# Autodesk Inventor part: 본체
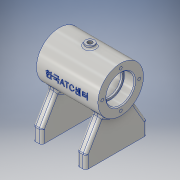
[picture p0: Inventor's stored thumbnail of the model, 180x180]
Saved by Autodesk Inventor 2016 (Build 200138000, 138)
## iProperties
Created: 2018-05
Part Number: 본체
Material: 알루미늄 6061
Document SubType Name: Modeling
Designer: USER
Mass: 317.695 g
Surface Area: 375.824 cm^2
Volume: 117.665 cm^3
Density: 2.7 g/cm^3
Appearance: 알루미늄 - 평지
Author: USER
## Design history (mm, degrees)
sketch "스케치1"
  geometry: L1 (-35, 0)-(35, 0); L2 (-35, 16)-(-35, 26); L3 (-35, 26)-(35, 26); L4 (35, 26)-(35, 16); L5 (35, 16)-(23, 16); L6 (23, 16)-(23, 14); L7 (23, 14)-(21, 14); L8 (21, 14)-(21, 21); L9 (21, 21)-(-21, 21); L10 (-21, 21)-(-21, 14); L11 (-21, 14)-(-23, 14); L12 (-23, 14)-(-23, 16); L13 (-23, 16)-(-35, 16); 2 further points
  constraints: 26 end point, 10 perpendicular, 2 point on line, 2 vertical, 1 coincident, 1 collinear, 1 horizontal, 1 midpoint
  dimensions: "d11" = 70 distance of L1.start L1.end; "d12" = 32 diameter of L13 L1; "d13" = 28 diameter of L11 L1; "d14" = 32 diameter of L5 L1; "d15" = 28 diameter of L7 L1; "d16" = 42 diameter of L9 L1; "d17" = 52 diameter of L3 L1; "d18" = 12 distance between parallel lines of L2 L12; "d19" = 12 distance of L4.end L5.end; "d20" = 42 distance of L8.end L9.end
revolve "회전1" sketch "스케치1" stored, may be unused: angle "d21" = 90 deg
node "작업 평면1"
sketch "스케치2"
  geometry: L1 (35, 26)-(35, -26) reference; C1 r 5 at (0, 0); 1 further point
  constraints: 1 centre point, 1 coincident
  dimensions: "d23" = 35 distance from line of C1.centre L1; "d24" = 10 diameter of C1
extrude "돌출1" join sketch "스케치2" stored distance "d25" = 0; taper "d26" = 0 deg
hole "구멍1" diameter "d29" = 5.188; stored, may be unused: countersink angle "d33" = 90 deg, drill point angle "d35" = 118 deg; dims "d27" = 10, "d28" = 10, "d30" = 12, "d31" = 4, "d32" = 2, "d34" = 16
sketch "스케치3"
  geometry: L1 (29, -5)-(25.515, -5) reference; L2 (25.515, 5)-(29, 5) reference; L3 (29, 5)-(29, 2.594) reference; L4 (29, 2.594)-(20.839, 2.594) reference; L5 (20.839, -2.594)-(29, -2.594) reference; L6 (29, -2.594)-(29, -5) reference; L7 (0, 0)-(-39.442, 0); L8 (0, 0)-(-27.251, -9.919); A1 r 26 centre (0, 0) between (25.515, 5) and (25.515, -5) reference; A2 r 21 centre (0, 0) between (20.839, 2.594) and (20.839, -2.594) reference; 1 further point
  constraints: 4 end point, 1 horizontal
  dimensions: "d36" = 20 deg angle of L7 L8; "d37" = 29 distance of L7.start L8.end
  node "절단 모서리 투영1"
node "작업 평면2"
sketch "스케치4"
  geometry: C1 r 6 at (0, 0); 2 further points
  constraints: 1 centre point, 1 coincident
  dimensions: "d38" = 12 diameter of C1
extrude "돌출2" join sketch "스케치4" stored distance "d39" = 10; taper "d40" = 0 deg
hole "구멍2" diameter "d43" = 5.188; stored, may be unused: countersink angle "d47" = 90 deg, drill point angle "d49" = 118 deg; dims "d41" = 10, "d42" = 10, "d44" = 12, "d45" = 4, "d46" = 2, "d48" = 16
node "작업 평면3"
sketch "스케치5"
  geometry: L1 (-19.386, 17.325)-(-50, 35); L2 (-50, 35)-(-65, 35); L3 (-65, 35)-(-65, -35); L4 (-65, -35)-(-50, -35); L5 (-50, -35)-(-19.386, -17.325); C1 r 16 at (0, 0) reference; A1 r 26 centre (0, 0) between (-19.386, 17.325) and (-19.386, -17.325) reference; A2 r 26 centre (0, 0) between (-19.386, 17.325) and (-19.386, -17.325) reference; 1 further point
  constraints: 10 end point, 4 point on circle, 2 perpendicular, 1 horizontal, 1 parallel
  dimensions: "d51" = 65 distance from line of L3 point (0, 0); "d52" = 15 distance of L1.end L2.end; "d53" = 30 deg angle of L1 L2; "d54" = 30 deg angle of L4 L5; "d55" = 70 distance of L2.end L3.end; "d56" = 35 distance from line of L4 point (0, 0)
extrude "돌출3" join sketch "스케치5" stored distance "d57" = 10; taper "d58" = 0 deg
sketch "스케치6" dims "d59" = 42
  geometry: 3 further points
  constraints: 2 vertical alignment, 1 coincident, 2 other
hole "구멍3" sketch "스케치6" at (0, 21) diameter "d60" = 3.242; stored, may be unused: countersink angle "d64" = 90 deg, drill point angle "d66" = 118 deg; dims "d61" = 8, "d62" = 4, "d63" = 2, "d65" = 10
sketch "스케치7"
  geometry: L1 (60, 70)-(50, 70) reference; L2 (60, 0)-(50, 0) reference; L3 (0, 0)-(10, 0) reference; L4 (0, 70)-(10, 70) reference; 9 further points
  constraints: 4 midpoint, 4 vertical alignment
  dimensions: "d70" = 40 distance of point (55, 15) point (55, 55); "d71" = 15 distance from line of point (55, 55) L1; "d72" = 40 distance of point (5, 15) point (5, 55); "d73" = 15 distance from line of point (5, 55) L4
hole "구멍4" sketch "스케치7" at (55, 55), (55, 15), (5, 55), (5, 15) diameter "d74" = 4.134; stored, may be unused: countersink angle "d78" = 90 deg, drill point angle "d80" = 118 deg; dims "d75" = 8, "d76" = 4, "d77" = 2, "d79" = 10
node "작업 평면4"
sketch "스케치8"
  geometry: L1 (-35, -26)-(-35, 26) reference; L2 (-35, 26)-(35, 26) reference; 2 further points
  constraints: 1 other
  dimensions: "d82" = 35 distance from line of L1 point (0, 0); "d83" = 26 distance from line of L2 point (0, 0)
feature "엠보싱1" sketch "스케치8" dims "d25" = 0, "d84" = 0.5, "d85" = 0
fillet "모깎기1" dims "d86" = 3
fillet "모깎기2" dims "d87" = 3
fillet "모깎기3" dims "d88" = 3
fillet "모깎기4" dims "d89" = 3
fillet "모깎기5" dims "d90" = 2
chamfer "모따기1" distance "d91" = 1; stored, may be unused: second distance "d92" = 2, angle "d93" = 45 deg
fillet "모깎기6" dims "d94" = 0.3
fillet "모깎기7" dims "d95" = 3
node "솔리드1"
mirror "대칭1"
pattern_circular "원형 패턴1" dims angle "d68" = 360 deg
mirror "대칭2"
node "절단 모서리 투영2"
other parameters: "d22" = 29, "d50" = -25, "d81" = 40.5
